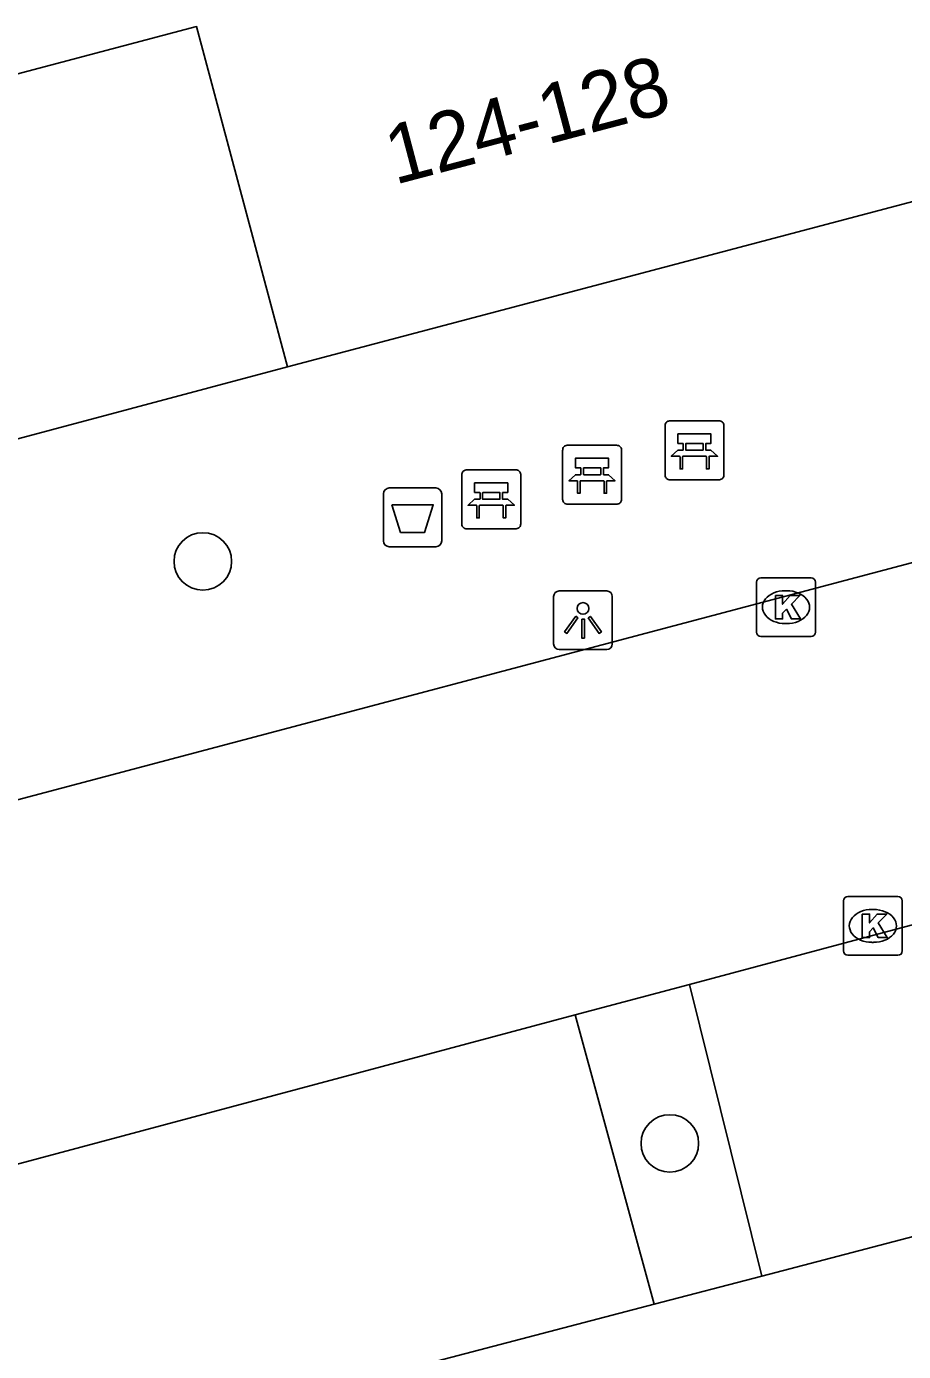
# Model space of a CAD drawing. Extents: x 162542 to 163144, y 380786 to 381511.
# Drawn here: x 162623.75 to 162638.64, y 381084.45 to 381106.97 of the extents above; entities that cross this region are included whole.
import ezdxf

# ---------------------------------------------------------------- set-up
doc = ezdxf.new("R2010")
doc.units = 0
for name, color, linetype in [('IMGEO_Afvalbak', 7, 'Continuous'), ('IMGEO_Bank', 7, 'Continuous'), ('IMGEO_Boom', 7, 'Continuous'), ('IMGEO_Kolk', 7, 'Continuous'), ('IMGEO_Lichtpunt', 7, 'Continuous'), ('IMGEO_Muur', 7, 'Continuous'), ('IMGEO_Pand', 7, 'Continuous'), ('IMGEO_Pand_nummerreeks', 7, 'Continuous'), ('IMGEO_Parkeervlak_open', 7, 'Continuous'), ('IMGEO_Rijbaan_lokaal_open', 7, 'Continuous'), ('IMGEO_Voetpad_open', 7, 'Continuous')]:
    doc.layers.add(name, color=color, linetype=linetype)

msp = doc.modelspace()

# ---------------------------------------------------------------- linework, layer by layer
at = {"layer": 'IMGEO_Afvalbak'}
for p, q in [((162629.809, 381098.231), (162629.809, 381099.031)), ((162629.809, 381099.031), (162629.809, 381098.231)), ((162629.909, 381099.131), (162630.699, 381099.131)), ((162630.699, 381099.131), (162629.909, 381099.131)), ((162630.799, 381099.031), (162630.799, 381098.231)), ((162630.799, 381098.231), (162630.799, 381099.031)), ((162630.699, 381098.131), (162629.909, 381098.131)), ((162629.909, 381098.131), (162630.699, 381098.131))]:
    msp.add_line(p, q, dxfattribs=at)
msp.add_lwpolyline([(162629.952, 381098.845), (162630.656, 381098.845), (162630.507, 381098.375), (162630.101, 381098.375), (162629.952, 381098.845)], dxfattribs=at)
for centre, start, end in [((162629.909, 381099.031), 90, 180), ((162629.909, 381099.031), 90, 180), ((162630.699, 381099.031), 0, 90), ((162630.699, 381099.031), 360, 90), ((162629.909, 381098.231), 180, 270), ((162629.909, 381098.231), 180, 270), ((162630.699, 381098.231), 270, 0), ((162630.699, 381098.231), 270, 0)]:
    msp.add_arc(centre, 0.1, start, end, dxfattribs=at)
at = {"layer": 'IMGEO_Bank'}
for p, q in [((162634.594, 381099.346), (162634.594, 381100.187)), ((162634.594, 381100.187), (162634.594, 381099.346)), ((162634.669, 381100.271), (162635.51, 381100.271)), ((162635.51, 381100.271), (162634.669, 381100.271)), ((162635.594, 381100.196), (162635.594, 381099.355)), ((162635.594, 381099.355), (162635.594, 381100.196)), ((162634.903, 381099.777), (162634.903, 381099.883)), ((162634.947, 381099.883), (162634.947, 381099.777)), ((162635.235, 381099.889), (162634.953, 381099.889)), ((162635.241, 381099.777), (162635.241, 381099.883)), ((162635.285, 381099.883), (162635.285, 381099.777)), ((162632.854, 381098.931), (162632.854, 381099.772)), ((162632.854, 381099.772), (162632.854, 381098.931)), ((162632.929, 381099.856), (162633.77, 381099.856)), ((162633.77, 381099.856), (162632.929, 381099.856)), ((162633.854, 381099.781), (162633.854, 381098.94)), ((162633.854, 381098.94), (162633.854, 381099.781)), ((162635.291, 381099.669), (162634.898, 381099.669)), ((162634.953, 381099.771), (162635.235, 381099.771)), ((162631.216, 381099.438), (162632.057, 381099.438)), ((162632.057, 381099.438), (162631.216, 381099.438)), ((162633.163, 381099.362), (162633.163, 381099.468)), ((162633.207, 381099.468), (162633.207, 381099.362)), ((162633.495, 381099.474), (162633.213, 381099.474)), ((162633.501, 381099.362), (162633.501, 381099.468)), ((162633.545, 381099.468), (162633.545, 381099.362)), ((162631.141, 381098.513), (162631.141, 381099.354)), ((162631.141, 381099.354), (162631.141, 381098.513)), ((162632.141, 381099.363), (162632.141, 381098.522)), ((162632.141, 381098.522), (162632.141, 381099.363)), ((162633.551, 381099.254), (162633.158, 381099.254)), ((162633.213, 381099.356), (162633.495, 381099.356)), ((162635.519, 381099.271), (162634.678, 381099.271)), ((162634.678, 381099.271), (162635.519, 381099.271)), ((162631.45, 381098.944), (162631.45, 381099.05)), ((162631.494, 381099.05), (162631.494, 381098.944)), ((162631.782, 381099.056), (162631.5, 381099.056)), ((162631.788, 381098.944), (162631.788, 381099.05)), ((162631.832, 381099.05), (162631.832, 381098.944)), ((162631.838, 381098.836), (162631.445, 381098.836)), ((162631.5, 381098.938), (162631.782, 381098.938)), ((162633.779, 381098.856), (162632.938, 381098.856)), ((162632.938, 381098.856), (162633.779, 381098.856)), ((162632.066, 381098.438), (162631.225, 381098.438)), ((162631.225, 381098.438), (162632.066, 381098.438))]:
    msp.add_line(p, q, dxfattribs=at)
for points in [[(162634.897, 381099.889), (162634.811, 381099.889), (162634.811, 381100.05), (162635.374, 381100.05), (162635.374, 381099.889), (162635.291, 381099.889)], [(162634.841, 381099.669), (162634.699, 381099.669), (162634.811, 381099.771), (162634.897, 381099.771)], [(162634.891, 381099.662), (162634.891, 381099.455), (162634.848, 381099.455), (162634.848, 381099.662)], [(162635.291, 381099.771), (162635.374, 381099.771), (162635.486, 381099.669), (162635.347, 381099.669)], [(162635.341, 381099.662), (162635.341, 381099.455), (162635.297, 381099.455), (162635.297, 381099.662)], [(162633.157, 381099.474), (162633.071, 381099.474), (162633.071, 381099.635), (162633.634, 381099.635), (162633.634, 381099.474), (162633.551, 381099.474)], [(162631.444, 381099.056), (162631.358, 381099.056), (162631.358, 381099.217), (162631.921, 381099.217), (162631.921, 381099.056), (162631.838, 381099.056)], [(162633.101, 381099.254), (162632.959, 381099.254), (162633.071, 381099.356), (162633.157, 381099.356)], [(162633.151, 381099.247), (162633.151, 381099.04), (162633.108, 381099.04), (162633.108, 381099.247)], [(162633.551, 381099.356), (162633.634, 381099.356), (162633.746, 381099.254), (162633.607, 381099.254)], [(162633.601, 381099.247), (162633.601, 381099.04), (162633.557, 381099.04), (162633.557, 381099.247)], [(162631.388, 381098.836), (162631.246, 381098.836), (162631.358, 381098.938), (162631.444, 381098.938)], [(162631.438, 381098.829), (162631.438, 381098.622), (162631.395, 381098.622), (162631.395, 381098.829)], [(162631.838, 381098.938), (162631.921, 381098.938), (162632.033, 381098.836), (162631.894, 381098.836)], [(162631.888, 381098.829), (162631.888, 381098.622), (162631.844, 381098.622), (162631.844, 381098.829)]]:
    msp.add_lwpolyline(points, dxfattribs=at)
for centre, radius, start, end in [((162634.672, 381100.193), 0.0779, 92.4484, 184.2845), ((162634.672, 381100.193), 0.0779, 92.4484, 184.2845), ((162635.516, 381100.193), 0.0779, 2.4484, 94.2845), ((162635.516, 381100.193), 0.0779, 2.4484, 94.2845), ((162634.896, 381099.882), 0.00671, 2.8957, 87.1043), ((162634.953, 381099.882), 0.00671, 92.8957, 177.1043), ((162635.235, 381099.882), 0.00671, 2.8957, 87.1043), ((162635.292, 381099.882), 0.00671, 92.8957, 177.1043), ((162632.932, 381099.778), 0.0779, 92.4484, 184.2845), ((162632.932, 381099.778), 0.0779, 92.4484, 184.2845), ((162633.776, 381099.778), 0.0779, 2.4484, 94.2845), ((162633.776, 381099.778), 0.0779, 2.4484, 94.2845), ((162634.841, 381099.662), 0.00671, 2.8957, 87.1043), ((162634.898, 381099.662), 0.00671, 92.8957, 177.1043), ((162634.896, 381099.778), 0.00671, 272.8957, 357.1043), ((162634.953, 381099.778), 0.00671, 182.8957, 267.1043), ((162635.235, 381099.778), 0.00671, 272.8957, 357.1043), ((162635.292, 381099.778), 0.00671, 182.8957, 267.1043), ((162635.29, 381099.662), 0.00671, 2.8957, 87.1043), ((162635.347, 381099.662), 0.00671, 92.8957, 177.1043), ((162631.219, 381099.36), 0.0779, 92.4484, 184.2845), ((162631.219, 381099.36), 0.0779, 92.4484, 184.2845), ((162632.063, 381099.36), 0.0779, 2.4484, 94.2845), ((162632.063, 381099.36), 0.0779, 2.4484, 94.2845), ((162633.156, 381099.467), 0.00671, 2.8957, 87.1043), ((162633.213, 381099.467), 0.00671, 92.8957, 177.1043), ((162633.495, 381099.467), 0.00671, 2.8957, 87.1043), ((162633.552, 381099.467), 0.00671, 92.8957, 177.1043), ((162633.101, 381099.247), 0.00671, 2.8957, 87.1043), ((162633.158, 381099.247), 0.00671, 92.8957, 177.1043), ((162633.156, 381099.363), 0.00671, 272.8957, 357.1043), ((162633.213, 381099.363), 0.00671, 182.8957, 267.1043), ((162633.495, 381099.363), 0.00671, 272.8957, 357.1043), ((162633.552, 381099.363), 0.00671, 182.8957, 267.1043), ((162633.55, 381099.247), 0.00671, 2.8957, 87.1043), ((162633.607, 381099.247), 0.00671, 92.8957, 177.1043), ((162634.672, 381099.349), 0.0779, 182.4484, 274.2845), ((162634.672, 381099.349), 0.0779, 182.4484, 274.2845), ((162635.516, 381099.349), 0.0779, 272.4484, 4.2845), ((162635.516, 381099.349), 0.0779, 272.4484, 4.2845), ((162631.443, 381099.049), 0.00671, 2.8957, 87.1043), ((162631.5, 381099.049), 0.00671, 92.8957, 177.1043), ((162631.782, 381099.049), 0.00671, 2.8957, 87.1043), ((162631.839, 381099.049), 0.00671, 92.8957, 177.1043), ((162631.388, 381098.829), 0.00671, 2.8957, 87.1043), ((162631.445, 381098.829), 0.00671, 92.8957, 177.1043), ((162631.443, 381098.945), 0.00671, 272.8957, 357.1043), ((162631.5, 381098.945), 0.00671, 182.8957, 267.1043), ((162631.782, 381098.945), 0.00671, 272.8957, 357.1043), ((162631.839, 381098.945), 0.00671, 182.8957, 267.1043), ((162631.837, 381098.829), 0.00671, 2.8957, 87.1043), ((162631.894, 381098.829), 0.00671, 92.8957, 177.1043), ((162632.932, 381098.934), 0.0779, 182.4484, 274.2845), ((162632.932, 381098.934), 0.0779, 182.4484, 274.2845), ((162633.776, 381098.934), 0.0779, 272.4484, 4.2845), ((162633.776, 381098.934), 0.0779, 272.4484, 4.2845), ((162631.219, 381098.516), 0.0779, 182.4484, 274.2845), ((162631.219, 381098.516), 0.0779, 182.4484, 274.2845), ((162632.063, 381098.516), 0.0779, 272.4484, 4.2845), ((162632.063, 381098.516), 0.0779, 272.4484, 4.2845)]:
    msp.add_arc(centre, radius, start, end, dxfattribs=at)
at = {"layer": 'IMGEO_Boom'}
for centre in [(162626.741, 381097.882), (162634.675, 381087.99)]:
    msp.add_circle(centre, 0.489, dxfattribs=at)
at = {"layer": 'IMGEO_Kolk'}
for p, q in [((162636.147, 381096.679), (162636.147, 381097.531)), ((162636.222, 381097.605), (162637.074, 381097.605)), ((162637.148, 381097.531), (162637.148, 381096.679)), ((162636.635, 381097.385), (162636.66, 381097.385)), ((162636.658, 381096.825), (162636.633, 381096.825)), ((162637.074, 381096.605), (162636.222, 381096.605)), ((162637.623, 381091.262), (162637.623, 381092.114)), ((162637.698, 381092.188), (162638.55, 381092.188)), ((162638.624, 381092.114), (162638.624, 381091.262)), ((162638.111, 381091.968), (162638.136, 381091.968)), ((162638.134, 381091.408), (162638.109, 381091.408)), ((162638.55, 381091.188), (162637.698, 381091.188))]:
    msp.add_line(p, q, dxfattribs=at)
for points in [[(162636.147, 381096.679), (162636.147, 381097.531)], [(162636.222, 381097.605), (162637.074, 381097.605)], [(162637.148, 381097.531), (162637.148, 381096.679)], [(162636.468, 381097.305), (162636.591, 381097.305), (162636.591, 381097.154), (162636.721, 381097.305), (162636.885, 381097.305), (162636.739, 381097.154), (162636.892, 381096.905), (162636.74, 381096.905), (162636.655, 381097.069), (162636.591, 381097.002), (162636.591, 381096.905), (162636.468, 381096.905), (162636.468, 381097.305)], [(162637.074, 381096.605), (162636.222, 381096.605)], [(162637.623, 381091.262), (162637.623, 381092.114)], [(162637.698, 381092.188), (162638.55, 381092.188)], [(162638.624, 381092.114), (162638.624, 381091.262)], [(162637.944, 381091.888), (162638.067, 381091.888), (162638.067, 381091.737), (162638.197, 381091.888), (162638.361, 381091.888), (162638.215, 381091.737), (162638.368, 381091.488), (162638.216, 381091.488), (162638.131, 381091.652), (162638.067, 381091.585), (162638.067, 381091.488), (162637.944, 381091.488), (162637.944, 381091.888)], [(162638.55, 381091.188), (162637.698, 381091.188)]]:
    msp.add_lwpolyline(points, dxfattribs=at)
for centre, start, end in [((162636.224, 381097.529), 91.552, 178.448), ((162636.224, 381097.529), 91.552, 178.448), ((162637.072, 381097.529), 1.552, 88.448), ((162637.072, 381097.529), 1.552, 88.448), ((162636.224, 381096.681), 181.552, 268.448), ((162636.224, 381096.681), 181.552, 268.448), ((162637.072, 381096.681), 271.552, 358.448), ((162637.072, 381096.681), 271.552, 358.448), ((162637.7, 381092.112), 91.552, 178.448), ((162637.7, 381092.112), 91.552, 178.448), ((162638.548, 381092.112), 1.552, 88.448), ((162638.548, 381092.112), 1.552, 88.448), ((162637.7, 381091.264), 181.552, 268.448), ((162637.7, 381091.264), 181.552, 268.448), ((162638.548, 381091.264), 271.552, 358.448), ((162638.548, 381091.264), 271.552, 358.448)]:
    msp.add_arc(centre, 0.0765, start, end, dxfattribs=at)
for centre, major_axis, ratio, start_param, end_param in [((162636.634, 381097.105), (-0.387, 0.002), 0.722429, 4.712389, 7.853982), ((162636.659, 381097.105), (-0.39, 0.002), 0.717154, 1.570796, 4.712389), ((162638.11, 381091.688), (-0.387, 0.002), 0.722429, 4.712389, 7.853982), ((162638.135, 381091.688), (-0.39, 0.002), 0.717154, 1.570796, 4.712389)]:
    msp.add_ellipse(centre, major_axis=major_axis, ratio=ratio, start_param=start_param, end_param=end_param, dxfattribs=at)
at = {"layer": 'IMGEO_Lichtpunt'}
for p, q in [((162632.701, 381097.286), (162632.701, 381096.479)), ((162632.701, 381097.286), (162632.701, 381096.479)), ((162633.603, 381097.381), (162632.795, 381097.381)), ((162633.603, 381097.381), (162632.795, 381097.381)), ((162633.697, 381096.479), (162633.697, 381097.286)), ((162633.697, 381096.479), (162633.697, 381097.286)), ((162632.795, 381096.385), (162633.603, 381096.385)), ((162632.795, 381096.385), (162633.603, 381096.385))]:
    msp.add_line(p, q, dxfattribs=at)
for points in [[(162633.075, 381096.95), (162633.114, 381096.922), (162632.926, 381096.66), (162632.888, 381096.687), (162633.075, 381096.95)], [(162633.177, 381096.902), (162633.224, 381096.902), (162633.224, 381096.58), (162633.177, 381096.58), (162633.177, 381096.902)], [(162633.287, 381096.922), (162633.325, 381096.949), (162633.512, 381096.687), (162633.473, 381096.659), (162633.287, 381096.922)]]:
    msp.add_lwpolyline(points, dxfattribs=at)
msp.add_circle((162633.2, 381097.084), 0.0994, dxfattribs=at)
for centre, start, end in [((162632.795, 381097.286), 90, 180), ((162632.795, 381097.286), 90, 180), ((162633.603, 381097.286), 0, 90), ((162633.603, 381097.286), 0, 90), ((162632.795, 381096.479), 180, 270), ((162632.795, 381096.479), 180, 270), ((162633.603, 381096.479), 270, 0), ((162633.603, 381096.479), 270, 360)]:
    msp.add_arc(centre, 0.0946, start, end, dxfattribs=at)
at = {"layer": 'IMGEO_Muur'}
msp.add_lwpolyline([(162628.178, 381101.192), (162622.828, 381099.762)], dxfattribs=at)
at = {"layer": 'IMGEO_Pand'}
for points in [[(162621.283, 381105.559), (162626.635, 381106.974), (162628.178, 381101.192)], [(162640.197, 381104.368), (162628.178, 381101.192)]]:
    msp.add_lwpolyline(points, dxfattribs=at)
at = {"layer": 'IMGEO_Parkeervlak_open'}
for points in [[(162635.01, 381090.694), (162636.24, 381085.737)], [(162634.411, 381085.258), (162633.065, 381090.174)]]:
    msp.add_lwpolyline(points, dxfattribs=at)
at = {"layer": 'IMGEO_Rijbaan_lokaal_open'}
for points in [[(162642.433, 381098.828), (162619.27, 381092.687), (162589.233, 381084.7), (162589.109, 381084.669), (162588.555, 381084.517)], [(162635.01, 381090.694), (162642.224, 381092.624)], [(162633.065, 381090.174), (162635.01, 381090.694)], [(162620.98, 381086.94), (162633.065, 381090.174)]]:
    msp.add_lwpolyline(points, dxfattribs=at)
at = {"layer": 'IMGEO_Voetpad_open'}
for points in [[(162628.178, 381101.192), (162622.828, 381099.762)], [(162643.545, 381087.651), (162636.24, 381085.737)], [(162636.24, 381085.737), (162634.411, 381085.258)], [(162634.411, 381085.258), (162622.272, 381082.078)]]:
    msp.add_lwpolyline(points, dxfattribs=at)

# ---------------------------------------------------------------- texts
at = {"layer": 'IMGEO_Pand_nummerreeks'}
msp.add_text('124-128', height=1, rotation=14.8017, dxfattribs=at).set_placement((162630.002, 381104.281))

doc.saveas('drawing.dxf')
